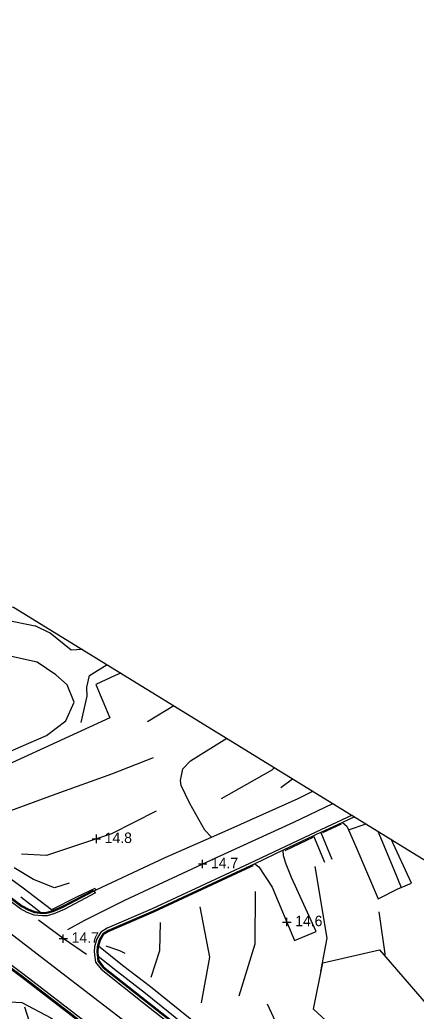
# Model space of a CAD drawing. Extents: x 2316231 to 2323598, y 363169 to 371906.
# Drawn here: x 2319524.2 to 2319713.6, y 366768.5 to 367241.8 of the extents above; entities that cross this region are included whole.
import ezdxf

# ---------------------------------------------------------------- set-up
doc = ezdxf.new("R2010")
doc.units = 0
for name, color, linetype in [('RD_DTM_BkLn1', 7, 'Continuous'), ('RD_DTM_Holes', 7, 'Continuous'), ('RD_DTM_TinHull', 7, 'Continuous'), ('RD_DTM_Void', 7, 'Continuous'), ('RD_EX_Road', 7, 'Continuous')]:
    doc.layers.add(name, color=color, linetype=linetype)

msp = doc.modelspace()

# ---------------------------------------------------------------- linework, layer by layer
at = {"layer": 'RD_DTM_BkLn1'}
for p, q in [((2319585.12, 366906.724), (2319597.762, 366914.365)), ((2319605.748, 366888.021), (2319623.091, 366898.802)), ((2319648.886, 366875.266), (2319654.529, 366879.486))]:
    msp.add_line(p, q, dxfattribs=at)
for points in [[(2319483.128, 366959.186), (2319491.691, 366962.134), (2319497.812, 366961.054), (2319508.694, 366954.044), (2319517.288, 366955.409), (2319531.568, 366952.486)], [(2319554.076, 366941.205), (2319548.65, 366940.808), (2319538.603, 366949.02), (2319531.568, 366952.486)], [(2319546.238, 366907.177), (2319550.16, 366916.006), (2319546.81, 366924.312), (2319541.348, 366929.074), (2319532.465, 366935.178), (2319520.244, 366937.829)], [(2319553.494, 366906.316), (2319556.372, 366918.956), (2319556.224, 366923.166), (2319557.401, 366928.783), (2319565.904, 366933.938)], [(2319476.569, 366872.268), (2319488.088, 366876.93), (2319500.02, 366883.501), (2319507.729, 366887.357), (2319524.815, 366894.859), (2319536.895, 366900.183), (2319546.238, 366907.177)], [(2319587.953, 366889.38), (2319567.974, 366881.642), (2319541.459, 366872.035), (2319508.688, 366860.184)], [(2319620.605, 366870.046), (2319644.825, 366883.741), (2319645.825, 366884.834)], [(2319547.189, 366807.443), (2319555.27, 366811.984), (2319574.422, 366821.513), (2319618.207, 366841.864), (2319655.212, 366858.656), (2319673.852, 366867.614)], [(2319589.378, 366863.972), (2319567.977, 366853.198), (2319536.884, 366842.817), (2319524.941, 366843.401)], [(2319547.738, 366829.653), (2319540.699, 366827.449), (2319530.681, 366831.368), (2319521.503, 366836.996)], [(2319668.085, 366787.375), (2319671.038, 366803.282), (2319665.37, 366837.586)], [(2319636.599, 366825.638), (2319636.427, 366800.439), (2319628.896, 366775.687)], [(2319611, 366772.449), (2319615.023, 366794.32), (2319610.322, 366818.304)], [(2319698.733, 366794.72), (2319698.743, 366795.882), (2319695.964, 366815.968)], [(2319556.114, 366795.482), (2319545.395, 366802.789), (2319533.033, 366811.997)], [(2319591.242, 366810.77), (2319590.893, 366797.262), (2319586.793, 366784.632)], [(2320181.242, 366310.091), (2320155.019, 366325.446), (2320123.083, 366345.253), (2320086.948, 366368.753), (2320053.703, 366393.27), (2320025.668, 366415.513), (2319990.392, 366443.393), (2319961.2, 366465.398), (2319946.981, 366477.722), (2319911.261, 366503.831), (2319880.301, 366528.217), (2319842.976, 366556.718), (2319811.094, 366581.051), (2319781.152, 366604.205), (2319750.318, 366628.239), (2319715.24, 366656.141), (2319656.149, 366700.693), (2319623.266, 366725.395), (2319586.108, 366754.455), (2319538.084, 366791.417), (2319519.19, 366805.873)], [(2319574.493, 366796.033), (2319571.9, 366797.369), (2319565.416, 366799.467)], [(2319523.713, 366682.618), (2319520.433, 366685.837), (2319519.172, 366689.1), (2319517.268, 366693.885), (2319514.719, 366703.224), (2319509.801, 366721.19), (2319509.444, 366738.902), (2319510.778, 366748.005), (2319512.215, 366755.124), (2319513.544, 366761.73), (2319516.272, 366769.901), (2319519.408, 366772.948), (2319525.134, 366772.605), (2319539.014, 366765.347), (2319584.799, 366730.232), (2319642.331, 366684.582), (2319702.289, 366638.975), (2319719.814, 366625.793)], [(2319526.392, 366770.613), (2319528.837, 366763.13), (2319532.675, 366756.267), (2319539.813, 366743.968), (2319542.775, 366735.326), (2319542.552, 366733.437)]]:
    msp.add_lwpolyline(points, dxfattribs=at)
at = {"layer": 'RD_DTM_Holes'}
msp.add_lwpolyline([(2319806.828, 366803.309), (2319840.027, 366780.448), (2319826.686, 366757.358), (2319805.808, 366744.632), (2319789.842, 366725.048), (2319788.697, 366704.347), (2319785.341, 366687.804), (2319773.529, 366673.476), (2319750.828, 366672.08), (2319740.54, 366699.66), (2319735.954, 366697.837), (2319727.417, 366672.765), (2319709.263, 366667.546), (2319675.193, 366696.059), (2319671.085, 366716.364), (2319682.373, 366752.991), (2319664.472, 366769.482), (2319668.928, 366791.548), (2319696.131, 366797.732), (2319727.395, 366761.549), (2319765.101, 366778.43), (2319806.828, 366803.309)], dxfattribs=at)
at = {"layer": 'RD_DTM_TinHull'}
msp.add_lwpolyline([(2318009.783, 367630.234), (2318999.407, 367049.655), (2319281.252, 367000.442), (2319521.217, 366961.394), (2320716.689, 366226.888), (2320934.852, 366280.749), (2321141.465, 366502.562), (2321263.978, 366719.924), (2321282.537, 366948.249), (2321279.947, 367175.232), (2321214.652, 367465.641), (2321221.515, 367818.629), (2321207.427, 368150.673), (2321267.86, 368369.229), (2321400.963, 368599.408), (2321534.916, 368777.939)], dxfattribs=at)
at = {"layer": 'RD_DTM_Void'}
for p, q in [((2319560.742, 366848.782), (2319560.742, 366852.782)), ((2319558.742, 366850.782), (2319562.742, 366850.782)), ((2319609.54, 366838.765), (2319613.54, 366838.765)), ((2319611.54, 366836.765), (2319611.54, 366840.765)), ((2319649.798, 366811.055), (2319653.798, 366811.055)), ((2319651.798, 366809.055), (2319651.798, 366813.055)), ((2319544.949, 366801.121), (2319544.949, 366805.121)), ((2319542.949, 366803.121), (2319546.949, 366803.121))]:
    msp.add_line(p, q, dxfattribs=at)
at = {"layer": 'RD_EX_Road'}
for p, q in [((2319678.395, 366858.592), (2319668, 366853.808)), ((2319677.755, 366857.747), (2319668.888, 366853.666)), ((2319684.193, 366861.261), (2319678.395, 366858.592)), ((2319681.209, 366855.029), (2319689.72, 366857.865)), ((2319664.539, 366852.19), (2319650.057, 366845.296)), ((2319664.539, 366852.19), (2319669.823, 366839.561)), ((2319668, 366853.808), (2319673.344, 366841.033)), ((2319664.165, 366851.458), (2319650.858, 366845.123)), ((2319650.057, 366845.296), (2319636.458, 366838.821)), ((2319497.492, 366838.988), (2319524.965, 366818.43)), ((2319498.188, 366839.091), (2319525.194, 366818.874)), ((2319559.644, 366825.883), (2319560.635, 366826.347)), ((2319560.364, 366824.958), (2319559.644, 366825.883)), ((2319533.944, 366815.786), (2319524.614, 366822.881))]:
    msp.add_line(p, q, dxfattribs=at)
for points in [[(2319572.383, 366929.958), (2319569.813, 366928.786), (2319560.555, 366924.428), (2319567.154, 366908.539), (2319541.793, 366896.964), (2319520.271, 366887.125)], [(2319615.709, 366851.545), (2319612.626, 366854.934), (2319605.503, 366867.688), (2319601.222, 366876.211), (2319600.912, 366878.663), (2319602.046, 366884.127), (2319605.748, 366888.021)], [(2319615.709, 366851.545), (2319623.687, 366855.068), (2319657.145, 366870.064), (2319664.166, 366873.565)], [(2319524.413, 366817.364), (2319496.052, 366838.566), (2319461.777, 366865.359)], [(2319682.963, 366862.016), (2319665.622, 366854.035), (2319633.925, 366838.945), (2319587.437, 366817.341), (2319565.86, 366808.062), (2319562.908, 366806.285), (2319560.913, 366802.951), (2319559.932, 366799.376), (2319559.692, 366796.741), (2319560.313, 366791.953), (2319562.996, 366788.505), (2319584.266, 366771.664), (2319610.167, 366751.361), (2319629.311, 366737.545), (2319653.702, 366718.14), (2319673.91, 366702.399)], [(2319678.395, 366858.592), (2319680.4, 366856.815), (2319681.209, 366855.029)], [(2319668, 366853.808), (2319666.131, 366852.948), (2319664.539, 366852.19)], [(2319681.209, 366855.029), (2319684.79, 366847.125), (2319695.411, 366822.155), (2319705.209, 366827.012), (2319706.496, 366827.557)], [(2319695.222, 366854.484), (2319702.881, 366836.186), (2319706.496, 366827.557)], [(2319525.694, 366827.249), (2319507.864, 366840.187), (2319498.278, 366847.394), (2319496.107, 366844.159), (2319496.126, 366842.324), (2319497.492, 366838.988)], [(2319560.635, 366826.347), (2319593.613, 366841.787), (2319615.709, 366851.545)], [(2319706.496, 366827.557), (2319711.305, 366829.595), (2319701.628, 366850.548)], [(2319636.458, 366838.821), (2319638.36, 366837.456), (2319644.862, 366827.67), (2319655.456, 366802.292), (2319665.822, 366806.514), (2319653.947, 366832.298), (2319651.436, 366838.708), (2319650.202, 366842.59), (2319650.057, 366845.296)], [(2319636.458, 366838.821), (2319634.436, 366837.859), (2319587.927, 366816.246), (2319566.409, 366806.992), (2319563.784, 366805.412), (2319562.027, 366802.475), (2319561.118, 366799.161), (2319560.899, 366796.764), (2319561.461, 366792.432), (2319563.854, 366789.356), (2319585.009, 366772.607), (2319605.123, 366756.84)], [(2319635.762, 366837.936), (2319634.649, 366837.406), (2319588.131, 366815.789), (2319566.638, 366806.546), (2319564.149, 366805.048), (2319562.491, 366802.277), (2319561.749, 366799.572)], [(2319739.365, 366619.499), (2319712.779, 366640.014), (2319683.432, 366662.695), (2319640.294, 366695.714), (2319602.28, 366724.947), (2319560.502, 366757.421), (2319525.144, 366784.587), (2319498.201, 366804.6), (2319457.591, 366836.119)], [(2319739.671, 366619.894), (2319713.085, 366640.41), (2319683.737, 366663.091), (2319640.599, 366696.111), (2319602.586, 366725.343), (2319560.808, 366757.817), (2319525.457, 366784.977), (2319498.503, 366804.998), (2319457.898, 366836.514)], [(2319458.695, 366837.54), (2319499.289, 366806.033), (2319526.24, 366786.015), (2319561.603, 366758.846), (2319603.381, 366726.371), (2319641.39, 366697.142), (2319684.529, 366664.122), (2319713.879, 366641.439)], [(2319560.364, 366824.958), (2319545.341, 366817.046), (2319540.473, 366814.909), (2319537.306, 366814.032), (2319534.972, 366813.978), (2319530.961, 366814.368), (2319527.75, 366815.638), (2319524.413, 366817.364)], [(2319524.965, 366818.43), (2319528.247, 366816.731), (2319531.245, 366815.546), (2319535.016, 366815.18), (2319537.129, 366815.229), (2319540.07, 366816.043), (2319544.82, 366818.127), (2319559.644, 366825.883)], [(2319560.635, 366826.347), (2319560.075, 366827.013), (2319551.203, 366822.886), (2319539.332, 366816.877), (2319525.694, 366827.249)], [(2319533.944, 366815.786), (2319535.034, 366815.68), (2319537.055, 366815.727), (2319539.902, 366816.515), (2319544.603, 366818.578), (2319559.412, 366826.326)], [(2319525.194, 366818.874), (2319528.455, 366817.187), (2319531.364, 366816.036), (2319533.944, 366815.786)], [(2319561.749, 366799.572), (2319561.611, 366799.071), (2319561.402, 366796.773), (2319561.69, 366794.554)], [(2319614.644, 366757.461), (2319586.657, 366780.106), (2319573.317, 366790.327), (2319561.749, 366799.572)], [(2319609.285, 366756.708), (2319584.209, 366776.997), (2319570.879, 366787.211), (2319561.69, 366794.554)], [(2319561.69, 366794.554), (2319561.939, 366792.631), (2319564.212, 366789.71), (2319585.318, 366772.999), (2319604.687, 366757.817)], [(2319638.81, 366740.545), (2319636.795, 366745.101), (2319635.437, 366751.282), (2319649.084, 366757.629), (2319642.555, 366771.848)]]:
    msp.add_lwpolyline(points, dxfattribs=at)

# ---------------------------------------------------------------- texts
at = {"layer": 'RD_DTM_Void'}
for s, p in [('14.8', (2319564.742, 366848.782)), ('14.7', (2319615.54, 366836.765)), ('14.6', (2319655.798, 366809.055)), ('14.7', (2319548.949, 366801.121))]:
    msp.add_text(s, height=5, dxfattribs=at).set_placement(p)

doc.saveas('drawing.dxf')
